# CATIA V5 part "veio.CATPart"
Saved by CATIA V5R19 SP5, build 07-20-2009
Part number: veio
Bounding box of the stored display mesh (mm): x -8 to 8, y -20 to 20, z -7.954 to 7.954
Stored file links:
  Z:\UA\ATLAS\atlascar\ServoPiloto\dir\suportePotenciometro\V2\veio.CATPart
  Z:\programs_vbox\Dassault Systemes\B19\intel_a\reffiles\standard\MetricThickPitch.txt
  Z:\programs_vbox\Dassault Systemes\B19\intel_a\reffiles\standard\MetricThinPitch.txt
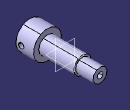
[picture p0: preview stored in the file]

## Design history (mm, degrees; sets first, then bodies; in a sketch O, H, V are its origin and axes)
Body1 (main body)
  Sketch1 on yz-plane, origin (0, 0, 0), H (0, 1, 0), V (0, 0, 1)
    line L1 (-20, 3) -> (-20, 8)
    line L2 (-20, 8) -> (-10, 8)
    line L3 (-10, 8) -> (-10, 5)
    line L4 (-10, 5) -> (10, 5)
    line L5 (20, 4) -> (20, 0)
    point P4 (20, 0)
    line L6 (20, 0) -> (-12, 0)
    line L7 (-12, 0) -> (-12, 3)
    line L8 (-12, 3) -> (-20, 3)
    line L9 (20, 4) -> (10, 4)
    line L10 (10, 4) -> (10, 5)
    distance L6 L8 = 3
    distance L6 L4 = 5
    distance L3 L7 = 2
    distance L5 L3 = 30
    distance L3 L1 = 10
    distance L6 L2 = 8
    distance L5 V = 20 {= (Sketch1.distance(L3 L1) +Sketch1.distance(L5 L3) )/2}
    distance L6 L9 = 4
    distance L5 L10 = 10
    vertical: L1 V, L3 V, L5 V, L7 V, L10 V
    horizontal: L2 H, L4 H, L6 H, L8 H, L9 H
    coincidence: P4 H
  Shaft1: profile Sketch1, axis Sketch1.H, angle 360
  Thread1: "M8", diameter 8, depth 10, pitch 1.25, on face of Shaft1 from Sketch1.L9, from face of Shaft1 from Sketch1.L5
  Sketch2 on face of Shaft1 from Sketch1.L5, origin (0, 20, 0), H (1, 0, 0), V (0, 0, -1)
    point P1 (0, 0)
  Hole1: placed by Sketch2, at (0, 20, 0) direction (0, -1, 0), diameter 3.42, depth 10
  Thread2: "M4", diameter 4, depth 10, pitch 0.7, on face of Hole1, from face of Shaft1 from Sketch1.L5
  Sketch3 on yz-plane, origin (0, 0, 0), H (0, 1, 0), V (0, 0, 1)
    circle A1 centre (-17, 0) radius 1.5
    point P1 (-17, 0)
    reference projected line E1 (-20, 8) -> (-20, -8) from edge [face of Shaft1 from Sketch1.L1 | face of Shaft1 from Sketch1.L2]
    radius A1 = 1.5
    distance P1 E1 = 3
    coincidence: P1 H
  Pocket1: profile Sketch3, direction (-1, 0, 0), through (limit type 6), opposite side through (limit type 6)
